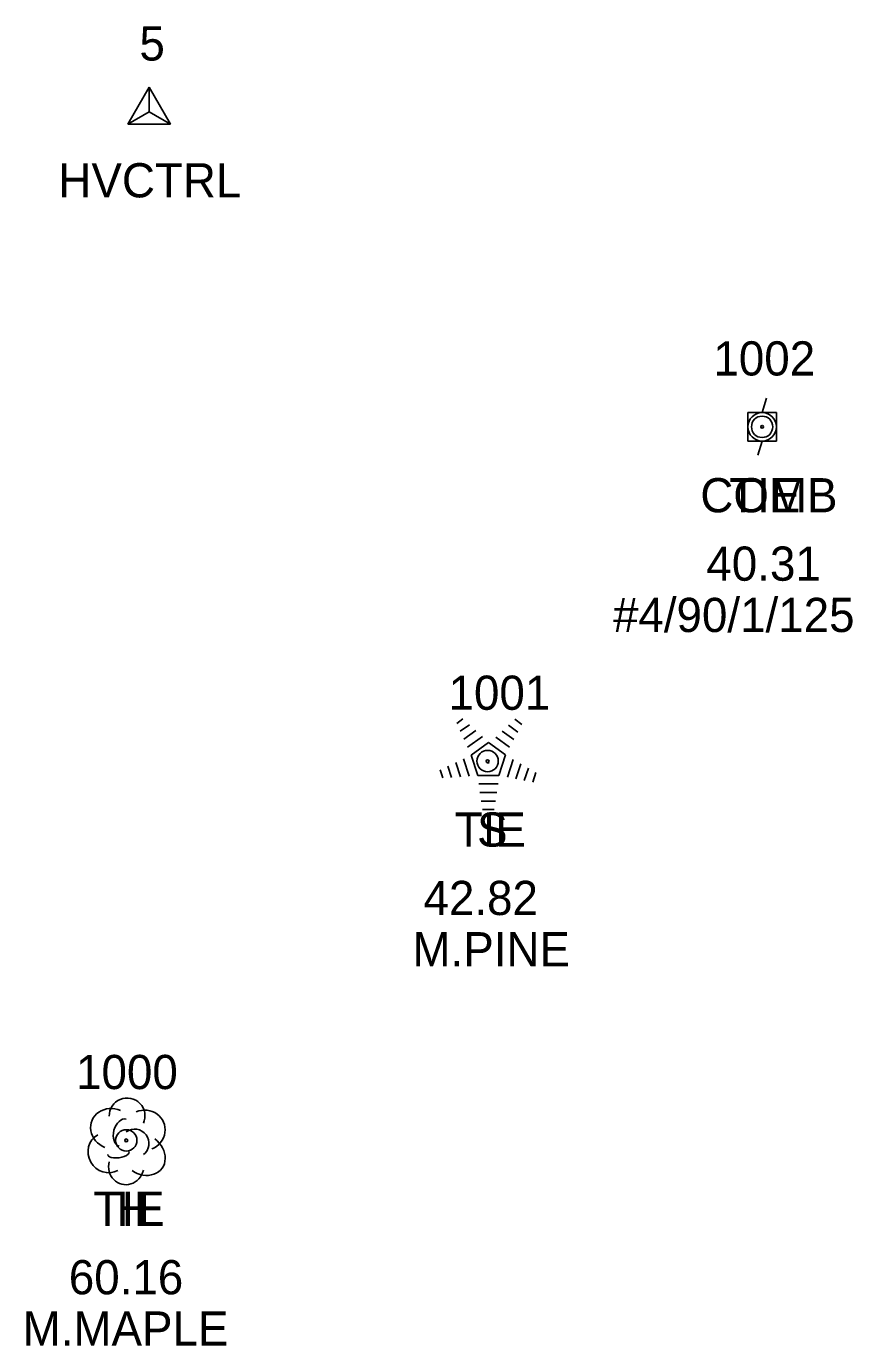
# Model space of a CAD drawing. Extents: x 1633660 to 1636532, y 388643 to 392631.
# Drawn here: x 1635317.7 to 1635366, y 390025.2 to 390102.3 of the extents above; entities that cross this region are included whole.
import ezdxf

# ---------------------------------------------------------------- set-up
doc = ezdxf.new("R2010")
doc.units = 0
for name, color, linetype in [('C_A', 7, 'Continuous'), ('C_I', 7, 'Continuous'), ('CBP', 7, 'Continuous'), ('CPSM', 7, 'Continuous'), ('L_A', 7, 'Continuous'), ('L_C', 7, 'Continuous'), ('L_I', 7, 'Continuous'), ('LTC', 7, 'Continuous'), ('LTD', 7, 'Continuous'), ('U_A', 7, 'Continuous'), ('U_C', 7, 'Continuous'), ('U_I', 7, 'Continuous'), ('UP', 7, 'Continuous')]:
    doc.layers.add(name, color=color, linetype=linetype)

msp = doc.modelspace()

# ---------------------------------------------------------------- linework, layer by layer
at = {"layer": 'CBP'}
for centre, radius in [((1635360.752, 390078.927), 0.625), ((1635360.752, 390078.927), 0.0833), ((1635344.695, 390059.377), 0.625), ((1635344.695, 390059.377), 0.0833), ((1635323.565, 390037.198), 0.625), ((1635323.565, 390037.198), 0.0833)]:
    msp.add_circle(centre, radius, dxfattribs=at)
at = {"layer": 'CPSM'}
for p, q in [((1635323.65, 390096.623), (1635324.9, 390098.788)), ((1635326.15, 390096.623), (1635324.9, 390098.788)), ((1635324.9, 390097.344), (1635324.9, 390098.788)), ((1635323.65, 390096.623), (1635324.9, 390097.344)), ((1635323.65, 390096.623), (1635326.15, 390096.623)), ((1635324.9, 390097.344), (1635324.9, 390097.344)), ((1635324.9, 390097.344), (1635326.15, 390096.623))]:
    msp.add_line(p, q, dxfattribs=at)
at = {"layer": 'LTC'}
for p, q in [((1635342.89, 390061.585), (1635343.244, 390061.843)), ((1635343.099, 390061.12), (1635343.629, 390061.504)), ((1635343.309, 390060.654), (1635344.013, 390061.165)), ((1635345.546, 390061.129), (1635346.225, 390060.635)), ((1635345.917, 390061.477), (1635346.467, 390061.078)), ((1635346.288, 390061.825), (1635346.707, 390061.521)), ((1635343.519, 390060.188), (1635344.397, 390060.826)), ((1635343.743, 390059.733), (1635344.755, 390060.468)), ((1635344.755, 390060.468), (1635345.752, 390059.743)), ((1635345.175, 390060.78), (1635345.984, 390060.192)), ((1635343.743, 390059.733), (1635344.13, 390058.54)), ((1635345.752, 390059.743), (1635345.361, 390058.54)), ((1635341.922, 390058.864), (1635342.074, 390058.396)), ((1635342.378, 390059.081), (1635342.589, 390058.429)), ((1635342.833, 390059.298), (1635343.104, 390058.462)), ((1635343.289, 390059.514), (1635343.619, 390058.495)), ((1635346.189, 390059.472), (1635345.852, 390058.432)), ((1635346.634, 390059.221), (1635346.347, 390058.337)), ((1635347.079, 390058.971), (1635346.842, 390058.242)), ((1635345.361, 390058.54), (1635344.13, 390058.54)), ((1635345.322, 390058.04), (1635344.178, 390058.04)), ((1635347.523, 390058.721), (1635347.336, 390058.147)), ((1635345.239, 390057.54), (1635344.25, 390057.54)), ((1635345.155, 390057.04), (1635344.323, 390057.04)), ((1635345.071, 390056.54), (1635344.396, 390056.54))]:
    msp.add_line(p, q, dxfattribs=at)
at = {"layer": 'LTD'}
msp.add_line((1635323.565, 390037.198), (1635323.565, 390037.198), dxfattribs=at)
msp.add_line((1635323.565, 390037.198), (1635323.565, 390037.198), dxfattribs=at)
msp.add_arc((1635323.611, 390038.632), 1.047, 335.52715, 180.95627, dxfattribs=at)
for centre, major_axis, ratio, start_param, end_param in [((1635322.773, 390037.864), (1.21, -0.512), 0.895232, 1.570796, 4.712389), ((1635324.606, 390037.781), (-1.141, -0.483), 0.949671, 1.570796, 4.712389), ((1635323.356, 390037.656), (-0.208, -0.792), 0.645439, 3.141593, 6.283185), ((1635324.065, 390037.031), (-0.5, 0.667), 0.989748, 3.141593, 6.283185), ((1635322.481, 390036.489), (0.584, -1.042), 0.959034, 3.141593, 6.283185), ((1635324.565, 390036.364), (-1.09, 0.792), 0.841452, 1.570796, 4.712389), ((1635323.106, 390036.448), (-0.625, -0.083), 0.423636, 0, 3.141593), ((1635323.565, 390035.698), (0.265, 1.061), 0.942809, 1.570796, 4.712389)]:
    msp.add_ellipse(centre, major_axis=major_axis, ratio=ratio, start_param=start_param, end_param=end_param, dxfattribs=at)
at = {"layer": 'UP'}
for p, q in [((1635361.002, 390080.594), (1635360.752, 390079.761)), ((1635359.919, 390078.094), (1635359.919, 390079.761)), ((1635359.919, 390079.761), (1635361.585, 390079.761)), ((1635361.585, 390079.761), (1635361.585, 390078.094)), ((1635360.752, 390078.927), (1635360.752, 390078.927)), ((1635361.585, 390078.094), (1635359.919, 390078.094)), ((1635360.502, 390077.261), (1635360.752, 390078.094))]:
    msp.add_line(p, q, dxfattribs=at)
msp.add_circle((1635360.752, 390078.927), 0.833, dxfattribs=at)

# ---------------------------------------------------------------- texts
at = {"layer": 'C_A'}
for s, p in [('HVCTRL', (1635319.593, 390092.344)), ('TIE', (1635358.831, 390073.927)), ('TIE', (1635342.773, 390054.377)), ('TIE', (1635321.643, 390032.198))]:
    msp.add_text(s, height=2, dxfattribs=at).set_placement(p)
at = {"layer": 'C_I'}
for s, p in [('5', (1635324.333, 390100.344)), ('1002', (1635357.902, 390081.927)), ('1001', (1635342.411, 390062.377)), ('1000', (1635320.628, 390040.198))]:
    msp.add_text(s, height=2, dxfattribs=at).set_placement(p)
at = {"layer": 'L_A'}
for s, p in [('S', (1635344.081, 390054.377)), ('H', (1635322.998, 390032.198))]:
    msp.add_text(s, height=2, dxfattribs=at).set_placement(p)
at = {"layer": 'L_C'}
for s, p in [('42.82', (1635340.947, 390050.377)), ('M.PINE', (1635340.301, 390047.377)), ('60.16', (1635320.202, 390028.198)), ('M.MAPLE', (1635317.502, 390025.198))]:
    msp.add_text(s, height=2, dxfattribs=at).set_placement(p)
at = {"layer": 'L_I'}
for s, p in [('1001', (1635342.411, 390062.377)), ('1000', (1635320.628, 390040.198))]:
    msp.add_text(s, height=2, dxfattribs=at).set_placement(p)
at = {"layer": 'LTC'}
msp.add_text('.', height=1.037, rotation=270, dxfattribs=at).set_placement((1635344.637, 390059.481))
at = {"layer": 'U_A'}
msp.add_text('COMB', height=2, dxfattribs=at).set_placement((1635357.138, 390073.927))
at = {"layer": 'U_C'}
for s, p in [('40.31', (1635357.492, 390069.927)), ('#4/90/1/125', (1635352.028, 390066.927))]:
    msp.add_text(s, height=2, dxfattribs=at).set_placement(p)
at = {"layer": 'U_I'}
msp.add_text('1002', height=2, dxfattribs=at).set_placement((1635357.902, 390081.927))

doc.saveas('drawing.dxf')
